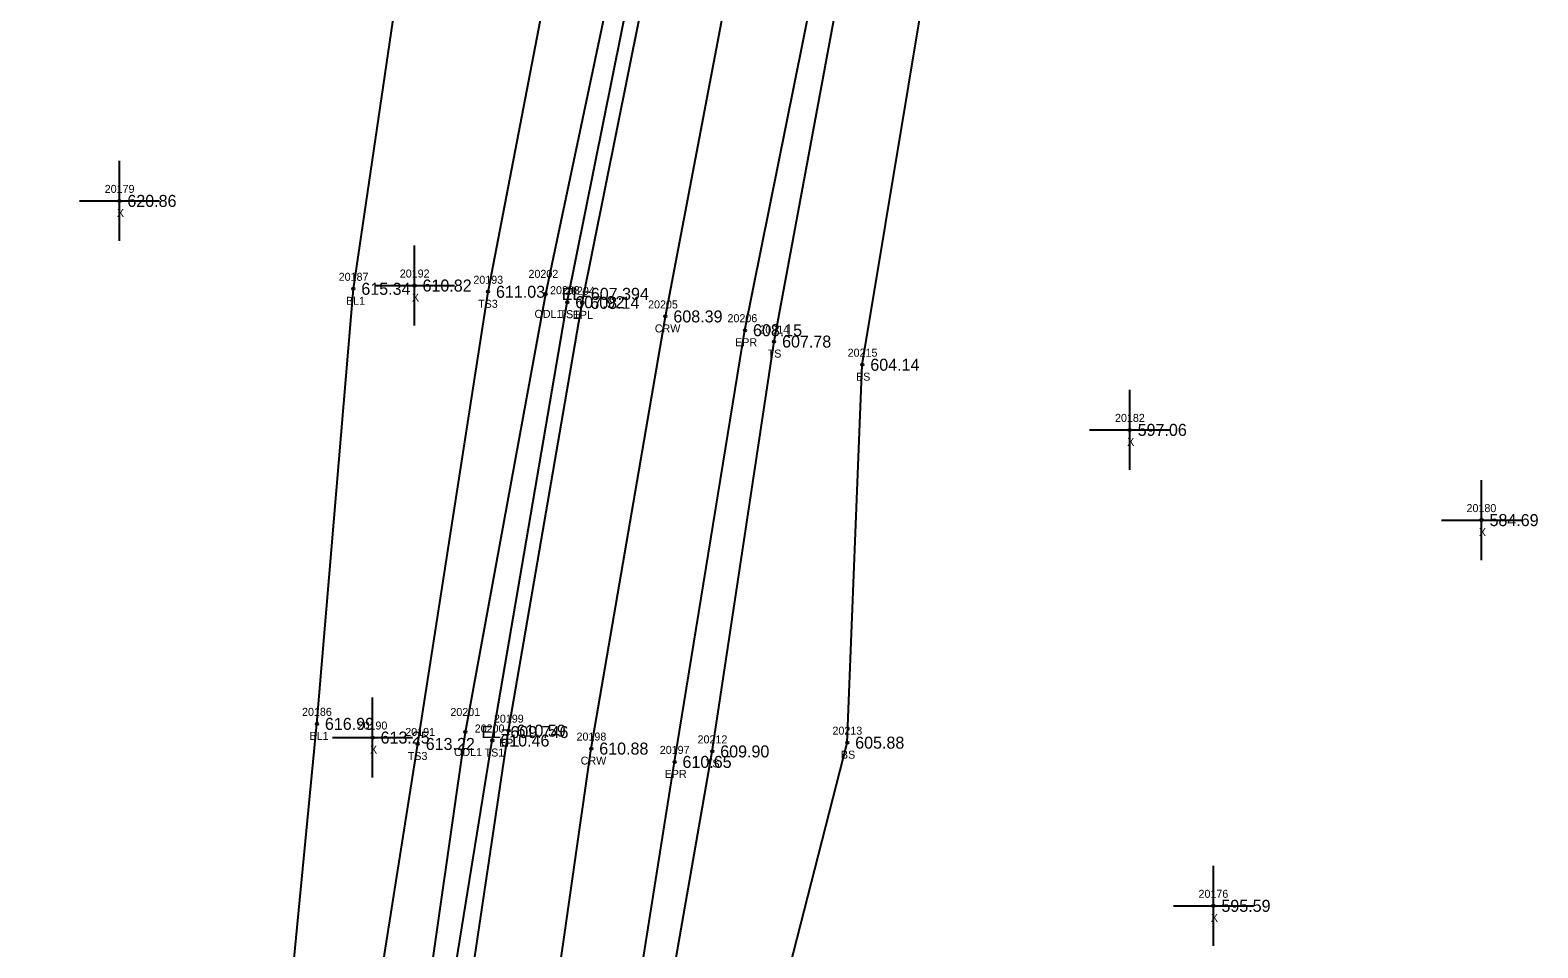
# Model space of a CAD drawing. Extents: x 1695443 to 1696344, y 1087542 to 1090645.
# Drawn here: x 1695882.4 to 1696070.7, y 1088207.5 to 1088322.1 of the extents above; entities that cross this region are included whole.
import ezdxf

# ---------------------------------------------------------------- set-up
doc = ezdxf.new("R2010")
doc.units = 0
for name, color, linetype in [('RD_DTM_BkLn1', 7, 'Continuous'), ('RD_DTM_BkLn2', 7, 'Continuous'), ('RD_DTM_BkLn_txCode', 7, 'Continuous'), ('RD_EX_H2O', 7, 'Continuous'), ('RD_EX_H2O_txCode', 7, 'Continuous'), ('RD_EX_Misc', 7, 'Continuous'), ('RD_EX_Misc_txCode', 7, 'Continuous'), ('RD_EX_Road', 7, 'Continuous'), ('RD_EX_Road_txCode', 7, 'Continuous'), ('RD_EX_TX_H2O_ELEV', 7, 'Continuous'), ('RD_EX_TX_Misc_ELEV', 7, 'Continuous'), ('RD_EX_TX_Road_ELEV', 7, 'Continuous'), ('RD_HC_Survey_ELEV', 7, 'Continuous'), ('RD_HC_Survey_txCode', 7, 'Continuous'), ('RD_SMD_Locator', 7, 'Continuous')]:
    doc.layers.add(name, color=color, linetype=linetype)

msp = doc.modelspace()

# ---------------------------------------------------------------- linework, layer by layer
at = {"layer": 'RD_DTM_BkLn1'}
for points in [[(1695869.23, 1087563.38), (1695882.71, 1087666.87), (1695895.39, 1087768.85), (1695908.05, 1087871.3), (1695919.71, 1087974.19), (1695925.35, 1088026.13), (1695931.27, 1088077.73), (1695937.88, 1088128.75), (1695945.4, 1088182.97), (1695952.48, 1088232.38), (1695961.74, 1088286.36), (1695971.36, 1088336.92), (1695982.91, 1088390.82), (1696009.16, 1088497.22), (1696035.45, 1088601.7), (1696045.5, 1088655.66), (1696049.03, 1088705.78), (1696045.47, 1088756.42), (1696033.82, 1088809.1), (1696016.78, 1088855.71), (1695990.89, 1088906.17), (1695964.41, 1088947.39), (1695931.21, 1088992.88)], [(1695919.84, 1088133.52), (1695913.76, 1088189.35), (1695918.21, 1088235.47), (1695922.76, 1088289.81), (1695929.86, 1088337.9), (1695944.4, 1088398.9), (1695974.86, 1088502.33), (1696013.19, 1088605.35)]]:
    msp.add_lwpolyline(points, dxfattribs=at)
at = {"layer": 'RD_DTM_BkLn2'}
for points in [[(1695957.06, 1088113.83), (1695958.4, 1088124.86), (1695969.72, 1088175.5), (1695984.45, 1088233.12), (1695986.34, 1088280.33), (1695995.02, 1088332.7), (1696009.2, 1088386.54), (1696038.3, 1088489.24), (1696061.78, 1088594.39), (1696062.98, 1088655.37), (1696069.05, 1088704.28), (1696065.26, 1088759.68), (1696052.53, 1088814.08), (1696046.96, 1088869.93), (1696016.66, 1088919.05), (1695997.75, 1088967.45), (1695944.59, 1089014.67), (1695937.23, 1089009.08)], [(1695916.78, 1088084), (1695925.73, 1088132.37), (1695932.55, 1088186.85), (1695940.12, 1088233.39), (1695949.48, 1088288.14), (1695959.7, 1088339.01), (1695971.73, 1088394.21), (1695997.36, 1088500.21), (1696023.08, 1088603.25), (1696032.92, 1088656.94), (1696036.1, 1088705.18), (1696032.76, 1088754.54), (1696021.34, 1088805.78), (1696004.42, 1088850.43), (1695979.2, 1088899.43), (1695947.85, 1088934.07), (1695935.29, 1088941.42), (1695930.1, 1088962.13), (1695923.44, 1088976.06), (1695917.46, 1088980.5), (1695920.03, 1088983.92)], [(1695811.33, 1088056.44), (1695848.8, 1088075.62), (1695896.28, 1088098.14), (1695916.78, 1088084), (1695919.84, 1088133.52), (1695923.64, 1088187.73), (1695930.8, 1088232.96), (1695939.58, 1088289.44), (1695949.3, 1088339.9), (1695960.86, 1088397.31), (1695988.69, 1088500.86), (1696013.19, 1088605.35), (1696020.87, 1088659.75), (1696023.4, 1088706.14), (1696018.3, 1088755.38), (1696009.58, 1088802.31), (1695993.24, 1088846.7), (1695969.88, 1088894.03), (1695962.8, 1088910.68)], [(1695882.6, 1087560.4), (1695895.55, 1087664.54), (1695908.06, 1087766.74), (1695920.67, 1087869.68), (1695933.47, 1087972.17), (1695938.06, 1088020.68), (1695943.39, 1088076.15), (1695950.93, 1088126.12), (1695958.62, 1088180.79), (1695967.59, 1088232.03), (1695975.32, 1088283.22), (1695985.14, 1088336.17), (1695996.59, 1088387.88), (1696023.18, 1088492.82), (1696049.23, 1088599.85), (1696058.32, 1088654.25)]]:
    msp.add_lwpolyline(points, dxfattribs=at)
at = {"layer": 'RD_EX_H2O'}
msp.add_lwpolyline([(1695916.78, 1088084), (1695923.72, 1088132.78), (1695929.91, 1088186.51), (1695936.75, 1088234.45), (1695946.8, 1088289.18), (1695957.47, 1088339.74), (1695969.14, 1088394.61), (1695994.85, 1088500.6), (1696021.07, 1088603.21), (1696031.1, 1088657.25), (1696033.92, 1088705.19), (1696029.81, 1088754.45), (1696018.23, 1088805.15), (1696001.4, 1088849.48), (1695973.58, 1088895.84), (1695962.8, 1088910.68)], dxfattribs=at)
at = {"layer": 'RD_EX_Misc'}
for p, q in [((1695893.53, 1088295.79), (1695893.53, 1088305.79)), ((1695888.53, 1088300.79), (1695898.53, 1088300.79)), ((1695930.4, 1088285.22), (1695930.4, 1088295.22)), ((1695925.4, 1088290.22), (1695935.4, 1088290.22)), ((1696019.74, 1088267.19), (1696019.74, 1088277.19)), ((1696014.74, 1088272.19), (1696024.74, 1088272.19)), ((1696063.69, 1088255.92), (1696063.69, 1088265.92)), ((1696058.69, 1088260.92), (1696068.69, 1088260.92)), ((1695925.16, 1088228.76), (1695925.16, 1088238.76)), ((1695920.16, 1088233.76), (1695930.16, 1088233.76)), ((1696030.2, 1088207.74), (1696030.2, 1088217.74)), ((1696025.2, 1088212.74), (1696035.2, 1088212.74))]:
    msp.add_line(p, q, dxfattribs=at)
at = {"layer": 'RD_EX_Road'}
for points in [[(1695879.87, 1087561.29), (1695893.33, 1087665.71), (1695905.96, 1087767.16), (1695918.66, 1087869.54), (1695930.87, 1087972.82), (1695936.26, 1088023.68), (1695942.14, 1088076.32), (1695948.07, 1088128.17), (1695955.04, 1088181.4), (1695962.88, 1088230.72), (1695971.68, 1088284.64), (1695982.02, 1088336.12), (1695993.28, 1088388.48), (1696018.75, 1088494.48), (1696045.23, 1088599.95), (1696055.72, 1088654.41), (1696060.15, 1088705.35), (1696055.83, 1088758.02), (1696044.01, 1088812.16), (1696026.4, 1088860.33), (1696000.41, 1088911.48), (1695972.46, 1088953.82), (1695939.48, 1088998.73), (1695931.21, 1088992.88)], [(1695858.19, 1087564.9), (1695871.71, 1087668.82), (1695884.5, 1087774.69), (1695887.48, 1087794.2), (1695897.57, 1087873.43), (1695908.92, 1087975.76), (1695914.49, 1088029.24), (1695917.65, 1088054.8), (1695920.27, 1088079.09), (1695926.98, 1088130.26), (1695934.75, 1088185.09), (1695942.15, 1088234.62), (1695951.36, 1088288.06), (1695961.48, 1088338.41), (1695972.86, 1088394.13), (1695998.53, 1088499.67), (1696024.81, 1088603.86), (1696034.83, 1088656.78)]]:
    msp.add_lwpolyline(points, dxfattribs=at)
at = {"layer": 'RD_SMD_Locator'}
for centre in [(1695893.53, 1088300.79), (1695922.76, 1088289.81), (1695930.4, 1088290.22), (1695939.58, 1088289.44), (1695946.8, 1088289.18), (1695949.48, 1088288.14), (1695951.36, 1088288.06), (1695961.74, 1088286.36), (1695971.68, 1088284.64), (1695975.32, 1088283.22), (1695986.34, 1088280.33), (1696019.74, 1088272.19), (1696063.69, 1088260.92), (1695918.21, 1088235.47), (1695936.75, 1088234.45), (1695942.15, 1088234.62), (1695925.16, 1088233.76), (1695930.8, 1088232.96), (1695940.12, 1088233.39), (1695952.48, 1088232.38), (1695967.59, 1088232.03), (1695984.45, 1088233.12), (1695962.88, 1088230.72), (1696030.2, 1088212.74)]:
    msp.add_circle(centre, 0.15, dxfattribs=at)

# ---------------------------------------------------------------- texts
at = {"layer": 'RD_DTM_BkLn_txCode'}
for s, p in [('20187', (1695920.93, 1088290.81)), ('20193', (1695937.75, 1088290.44)), ('BL1', (1695921.84, 1088287.81)), ('20203', (1695947.33, 1088289.14)), ('TS3', (1695938.34, 1088287.44)), ('TS1', (1695948.52, 1088286.14)), ('20214', (1695973.48, 1088284.22)), ('TS', (1695974.52, 1088281.22)), ('20215', (1695984.51, 1088281.33)), ('BS', (1695985.56, 1088278.33)), ('20186', (1695916.35, 1088236.47)), ('BL1', (1695917.29, 1088233.47)), ('20191', (1695929.25, 1088233.96)), ('20200', (1695937.92, 1088234.39)), ('20212', (1695965.76, 1088233.03)), ('20213', (1695982.61, 1088234.12)), ('TS1', (1695939.16, 1088231.39)), ('TS3', (1695929.56, 1088230.96)), ('TS', (1695966.8, 1088230.03)), ('BS', (1695983.67, 1088231.12))]:
    msp.add_text(s, height=1, dxfattribs=at).set_placement(p)
at = {"layer": 'RD_EX_H2O_txCode'}
for s, p in [('20202', (1695944.64, 1088291.18)), ('ODL1', (1695945.39, 1088286.18)), ('20201', (1695934.88, 1088236.45)), ('ODL1', (1695935.34, 1088231.45))]:
    msp.add_text(s, height=1, dxfattribs=at).set_placement(p)
at = {"layer": 'RD_EX_Misc_txCode'}
for s, p in [('20179', (1695891.7, 1088301.79)), ('X', (1695893.22, 1088298.79)), ('20192', (1695928.56, 1088291.22)), ('X', (1695930.08, 1088288.22)), ('20182', (1696017.91, 1088273.19)), ('X', (1696019.43, 1088270.19)), ('20180', (1696061.82, 1088261.92)), ('X', (1696063.37, 1088258.92)), ('20190', (1695923.29, 1088234.76)), ('X', (1695924.84, 1088231.76)), ('20176', (1696028.34, 1088213.74)), ('X', (1696029.88, 1088210.74))]:
    msp.add_text(s, height=1, dxfattribs=at).set_placement(p)
at = {"layer": 'RD_EX_Road_txCode'}
for s, p in [('20204', (1695949.2, 1088289.06)), ('EPL', (1695950.16, 1088286.06)), ('20206', (1695969.5, 1088285.64)), ('EPR', (1695970.45, 1088282.64)), ('20199', (1695940.32, 1088235.62)), ('EPL', (1695940.95, 1088232.62)), ('20197', (1695961.04, 1088231.72)), ('EPR', (1695961.65, 1088228.72))]:
    msp.add_text(s, height=1, dxfattribs=at).set_placement(p)
at = {"layer": 'RD_EX_TX_H2O_ELEV'}
for s, p in [('EL=607.394', (1695948.8, 1088288.43)), ('EL=609.746', (1695938.75, 1088233.7))]:
    msp.add_text(s, height=1.5, dxfattribs=at).set_placement(p)
at = {"layer": 'RD_EX_TX_Misc_ELEV'}
for s, p in [('620.86', (1695894.53, 1088300.04)), ('615.34', (1695923.76, 1088289.06)), ('610.82', (1695931.4, 1088289.47)), ('611.03', (1695940.58, 1088288.69)), ('607.92', (1695950.48, 1088287.39)), ('607.78', (1695976.32, 1088282.47)), ('604.14', (1695987.34, 1088279.58)), ('597.06', (1696020.74, 1088271.44)), ('584.69', (1696064.69, 1088260.17)), ('616.99', (1695919.21, 1088234.72)), ('613.25', (1695926.16, 1088233.01)), ('610.46', (1695941.12, 1088232.64)), ('613.22', (1695931.8, 1088232.21)), ('609.90', (1695968.59, 1088231.28)), ('605.88', (1695985.45, 1088232.37)), ('595.59', (1696031.2, 1088211.99))]:
    msp.add_text(s, height=1.5, dxfattribs=at).set_placement(p)
at = {"layer": 'RD_EX_TX_Road_ELEV'}
for s, p in [('608.14', (1695952.36, 1088287.31)), ('608.15', (1695972.68, 1088283.89)), ('610.59', (1695943.15, 1088233.87)), ('610.65', (1695963.88, 1088229.97))]:
    msp.add_text(s, height=1.5, dxfattribs=at).set_placement(p)
at = {"layer": 'RD_HC_Survey_ELEV'}
for s, p in [('608.39', (1695962.74, 1088285.61)), ('610.88', (1695953.48, 1088231.63))]:
    msp.add_text(s, height=1.5, dxfattribs=at).set_placement(p)
at = {"layer": 'RD_HC_Survey_txCode'}
for s, p in [('20205', (1695959.58, 1088287.36)), ('CRW', (1695960.42, 1088284.36)), ('20198', (1695950.64, 1088233.38)), ('CRW', (1695951.16, 1088230.38))]:
    msp.add_text(s, height=1, dxfattribs=at).set_placement(p)

doc.saveas('drawing.dxf')
